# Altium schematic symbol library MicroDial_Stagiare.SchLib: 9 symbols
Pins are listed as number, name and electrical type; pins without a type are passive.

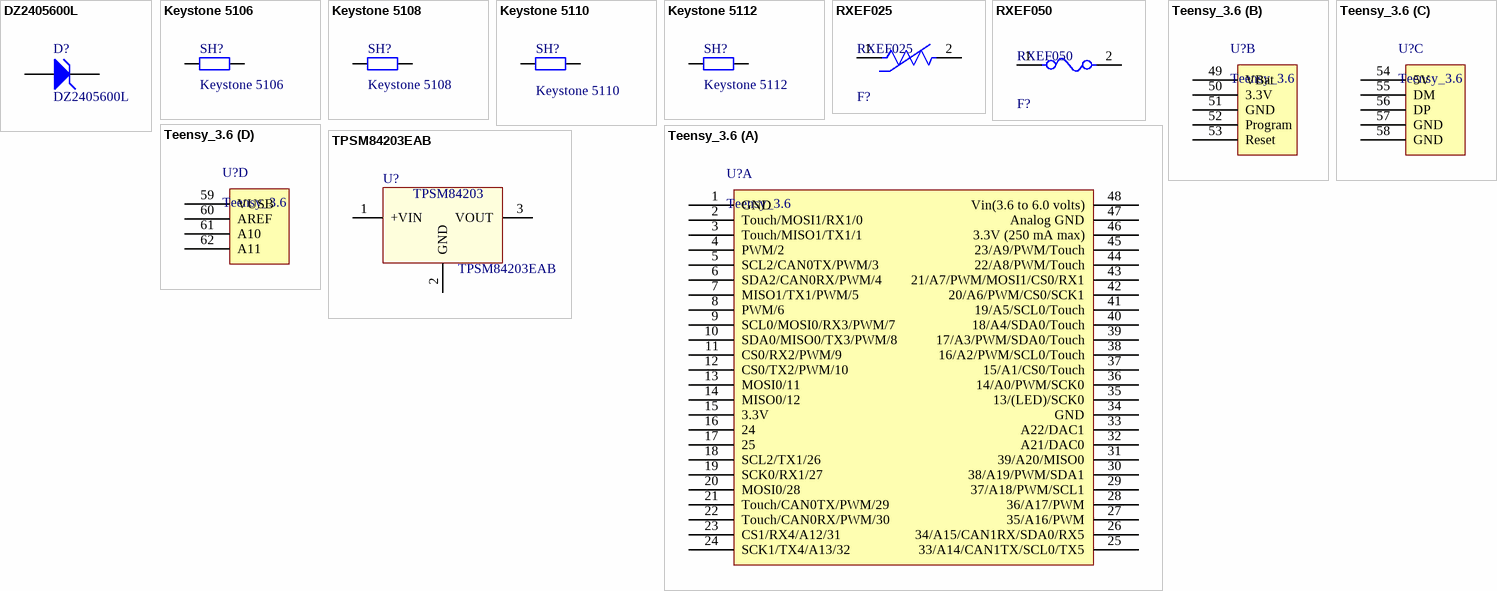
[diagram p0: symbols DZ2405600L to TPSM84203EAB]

## DZ2405600L
designator D?
DZ2405600L -  DIODE, ZENER, 2W, 5.6V, TMINIP2-F2-B, FULL REEL; Code Commande: RS760-2805
footprint TMiniP2-F2-B
pins: 1 A, 2 K

## Keystone 5106
designator SH?
HIGH CURRENT TRUE ZERO OHM SMT JUMPER Replacement for 0805 zero ohm chip set; Code Commande: Digikey 36-5106CT-ND
footprint KEYSTONE 5106 (Replacement for 0805 zero ohm chip set)
pins: 1, 2

## Keystone 5108
designator SH?
HIGH CURRENT TRUE ZERO OHM SMT JUMPER Replacement for 1206 zero ohm chip set; Code Commande: Digikey 36-5108CT-ND
footprint Keystone 5108 (Replacement for 1206 zero ohm chip set)
pins: 1, 2

## Keystone 5110
designator SH?
HIGH CURRENT TRUE ZERO OHM SMT JUMPERReplacement for 0603 zero ohm chip set; Code Commande: Digikey 36-5110CT-ND
footprint Keystone 5110 (Replacement for 0603 zero ohm chip set)
pins: 1, 2

## Keystone 5112
designator SH?
HIGH CURRENT TRUE ZERO OHM SMT JUMPER Replacement for 0402 zero ohm chip set; Code Commande: Digikey
footprint KEYSTONE 5112 (Replacement for 0402 zero ohm chip set)
pins: 1, 2

## RXEF025
designator F?
RXEF025 -  FUSE, PTC RESET, 72V, 250mA, RADIAL; Code Commande: F266-8022
footprint FP-RXEF025-MFG
pins: 1, 2

## RXEF050
designator F?
RXEF050 -  Fusible PPTC réarmable, broches radiales, Série PolySwitch RXEF, 72 VDC, 500 mA, 1 A, 4 s, Rond; Code Commande: F117-5864
footprint FP-RXEF050-MFG
pins: 1, 2

## Teensy_3.6
designator U?
32Bit Arduino Compatible Microcontrolleur; Code Commande: Digikey 1568-1465-ND / Mouser 474-DEV-14058
footprint Teensy3_6 (Teensy3_6 32 Bits Arduino-Compatible Microcontroleur)
footprint Teensy3_6 avec Support (Teensy3_6 32 Bits Arduino-Compatible Microcontroleur avec support HARWIN 4 X M20-7821246 et M20-7820546)
part A pins: 1 GND, 2 Touch/MOSI1/RX1/0, 3 Touch/MISO1/TX1/1, 4 PWM/2, 5 SCL2/CAN0TX/PWM/3, 6 SDA2/CAN0RX/PWM/4, 7 MISO1/TX1/PWM/5, 8 PWM/6, 9 SCL0/MOSI0/RX3/PWM/7, 10 SDA0/MISO0/TX3/PWM/8, 11 CS0/RX2/PWM/9, 12 CS0/TX2/PWM/10, 13 MOSI0/11, 14 MISO0/12, 15 3.3V, 16 24, 17 25, 18 SCL2/TX1/26, 19 SCK0/RX1/27, 20 MOSI0/28, 21 Touch/CAN0TX/PWM/29, 22 Touch/CAN0RX/PWM/30, 23 CS1/RX4/A12/31, 24 SCK1/TX4/A13/32, 25 33/A14/CAN1TX/SCL0/TX5, 26 34/A15/CAN1RX/SDA0/RX5, 27 35/A16/PWM, 28 36/A17/PWM, 29 37/A18/PWM/SCL1, 30 38/A19/PWM/SDA1, 31 39/A20/MISO0, 32 A21/DAC0, 33 A22/DAC1, 34 GND, 35 13/(LED)/SCK0, 36 14/A0/PWM/SCK0, 37 15/A1/CS0/Touch, 38 16/A2/PWM/SCL0/Touch, 39 17/A3/PWM/SDA0/Touch, 40 18/A4/SDA0/Touch, 41 19/A5/SCL0/Touch, 42 20/A6/PWM/CS0/SCK1, 43 21/A7/PWM/MOSI1/CS0/RX1, 44 22/A8/PWM/Touch, 45 23/A9/PWM/Touch, 46 3.3V (250 mA max), 47 Analog GND, 48 Vin(3.6 to 6.0 volts)
part B pins: 49 VBat, 50 3.3V, 51 GND, 52 Program, 53 Reset
part C pins: 54 5V, 55 DM, 56 DP, 57 GND, 58 GND
part D pins: 59 VUSB, 60 AREF, 61 A10, 62 A11

## TPSM84203EAB
designator U?
TPSM84203EAB -  Convertisseur DC/DC, 1 sortie, 4.95 W, 3.3 V, 1.5 A, TPSM842xx Family; Code Commande: F300-9711 / Mouser 595-TPSM84203EAB
footprint TPSM842XX SIPMODULE (TPSM842XX SIPMODULE (EAB0003A) TO-220 PowerModule)
pins: 1 +VIN, 2 GND, 3 VOUT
